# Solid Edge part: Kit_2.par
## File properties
Sűrűség: 0,000 kg/m^3
Pontosság: 0,990
Author: ahadarics
Last saved by: psaghy
Revision: 78
Username: ahadarics
Dokumentum tartalom típus: 0
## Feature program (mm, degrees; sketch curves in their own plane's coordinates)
base feature "unnamed BaseFeature 1"
sketch for "Furat_1" plane through (0, 0, 48) normal (0, 0, 1) x-axis (0.707107, -0.707107, 0)
  hole centre (0, 50.9117) bore radius 4.188
hole "Furat_1" nominal diameter 10 finite  VBottomAngle = 118 deg
sketch for "unnamed Hole 1" plane through (0, 0, 48) normal (0, 0, 1) x-axis (0.707107, -0.707107, 0)
  hole centre (-50.9117, 0) bore radius 4.188
hole "unnamed Hole 1" finite
sketch for "unnamed Hole 2" plane through (0, 0, 48) normal (0, 0, 1) x-axis (0.707107, -0.707107, 0)
  hole centre (0, -50.9117) bore radius 4.188
hole "unnamed Hole 2" finite
sketch for "unnamed Hole 3" plane through (0, 0, 48) normal (0, 0, 1) x-axis (0.707107, -0.707107, 0)
  hole centre (50.9117, 0) bore radius 4.188
hole "unnamed Hole 3" finite
pattern "unnamed Pattern 1" of "Furat_1", "unnamed Hole 1", "unnamed Hole 2", "unnamed Hole 3"
sketch for "Furat_5" plane through (46.5, -0.0074, 25.7488) normal (1, 0, 0) x-axis (0, 0, -1)
  hole centre (-6.2512, 7.0074) bore radius 7.475
hole "Furat_5" nominal diameter 16.662 finite  ThreadDepth = 17 mm
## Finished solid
Body 1: solid body, 572 faces, 1311 edges, 806 vertices, 7 internal voids.
  Faces by surface: cylinder 205, plane 152, cone 70, torus 54, sphere 53, spline 26, swept 12
  Edges by curve: curve on surface 497, circle 445, line 343, spline 26
Bounding box of the edges (mm; curved faces can reach further): 93.000 x 93.000 x 72.000, from (-46.5, -46.5, 8) to (46.5001, 46.5, 80).
Cylindrical faces by radius (mm): R0.3812 x2, R0.3829 x1, R0.3841 x2, R0.3867 x2, R0.3906 x1, R0.3923 x2, R0.4494 x1, R0.4682 x1, R0.4781 x1, R0.4828 x4, R0.4915 x2, R0.4958 x2, R0.5079 x2, R0.5081 x2, R0.5091 x1, R0.5418 x1, R0.5784 x1, R0.6016 x2, R0.6314 x2, R0.6541 x2, R0.6656 x2, R0.6796 x1, R0.6854 x1, R0.7231 x1, R0.756 x1, R0.7598 x2, R0.7606 x2, R0.7952 x1, R0.7968 x1, R0.8489 x1, R0.8923 x1, R0.9223 x1, R1 x43, R1.0009 x1, R1.0016 x19, R1.0018 x24, R1.01 x1, R1.0286 x1, R1.1393 x1, R1.2532 x1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
Conical faces (half-angle, radius in mm at the cone's reference point): 0.0028 deg R1.0012 x2, 0.0036 deg R1.0008 x6, 1 deg R23.75 x6, 1 deg R35 x6, 1.6538 deg R14.25 x1, 3.5477 deg R15.2454 x1, 5.1705 deg R12.9 x1, 8.3742 deg R12.5032 x1, 13.2989 deg R13.6846 x1, 14.7738 deg R13.2787 x1, 15 deg R21.1406 x1, 25.0169 deg R16.81 x1, 30 deg R6.1443 x1, 30 deg R14.8557 x2, 30 deg R15.1443 x1, 30 deg R22.125 x1, 38.6598 deg R31.7888 x6, 38.6598 deg R38.5 x1, 41.1859 deg R39.25 x3, 45 deg R3.75 x1, 45 deg R3.875 x1, 45 deg R5.3 x8, 45 deg R7.85 x8, 45 deg R8.67 x1, 45 deg R12.65 x2, 45 deg R17.85 x1, 59 deg R3.25 x1, 59 deg R4.188 x4
Toroidal faces (ring radius, tube radius in mm): R5.3 r0.3 x4, R5.7 r0.3 x1, R7.95 r0.2 x4, R8.65 r0.5 x4, R11.5 r1 x3, R12.8 r0.3 x1, R12.8088 r0.3 x1, R13.9279 r0.25 x1, R14.7464 r0.5 x1, R17.3 r0.2 x1, R19.75 r2 x1, R20.1163 r0.5 x1, R22.75 r1 x1, R23 r0.5 x1, R24.7327 r1 x6, R28.0969 r1 x6, R34.0061 r1 x6, R43 r1 x3, R46.9806 r1 x2, R47 r1 x6
Spherical faces by radius (mm): R1 x53
Planar faces by outward normal: +x 22, +y 8, +z 31, -x 1, -y 8, -z 23, oblique 59
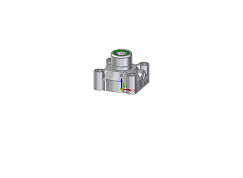
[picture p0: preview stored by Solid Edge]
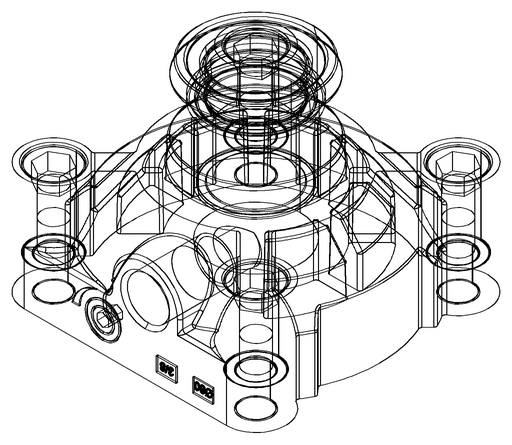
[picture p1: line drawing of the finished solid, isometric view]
